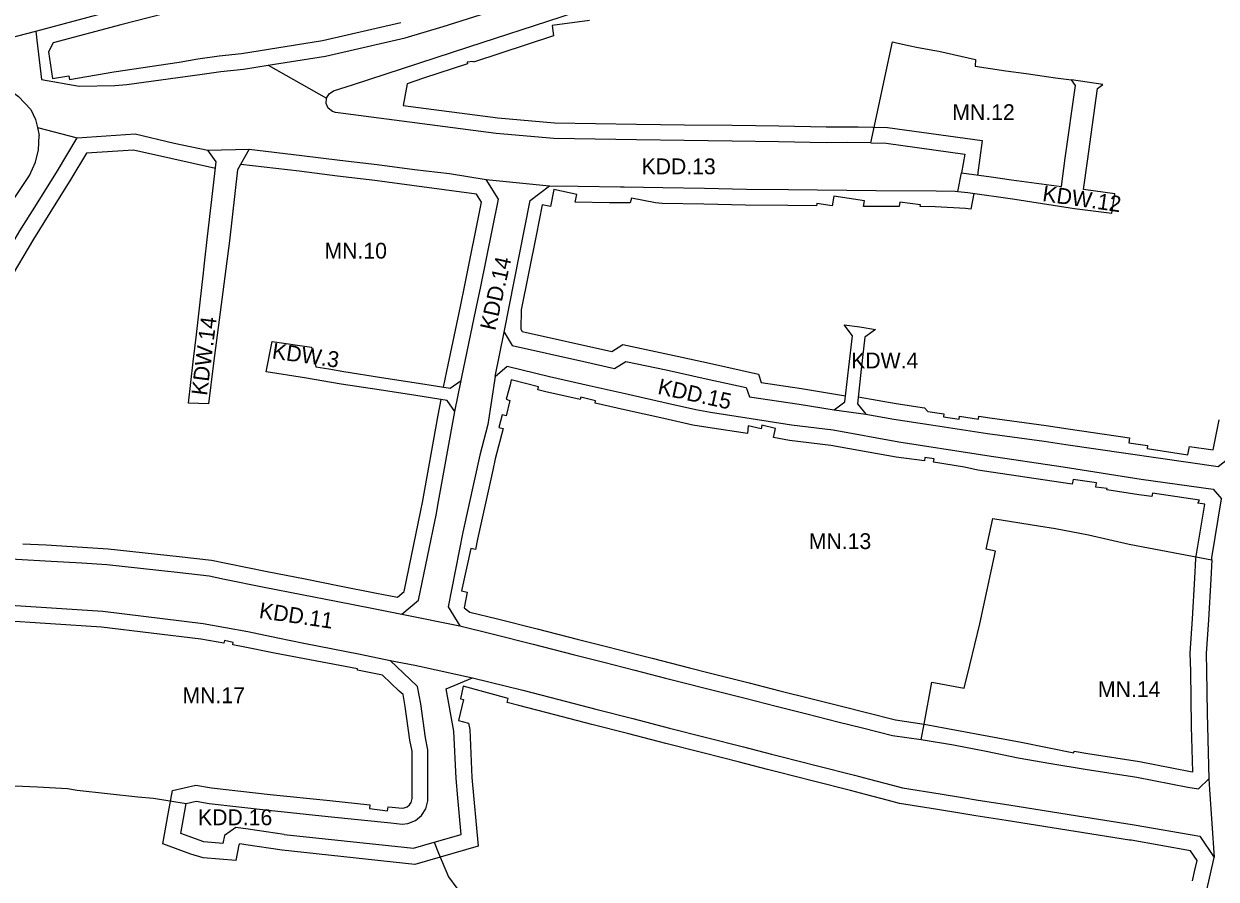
# Model space of a CAD drawing. Extents: x 7414808 to 7417449, y 5544732 to 5546764.
# Drawn here: x 7415519.6 to 7415895.6, y 5545621.3 to 5545891.1 of the extents above; entities that cross this region are included whole.
import ezdxf

# ---------------------------------------------------------------- set-up
doc = ezdxf.new("R2010")
doc.units = 0
for name, color, linetype in [('LIN_Linie Rozgraniczajace', 7, 'Continuous'), ('LIN_nieprzekraczale linie zabudowy', 7, 'Continuous'), ('TXT_Oznaczenia Przeznaczenia', 7, 'Continuous')]:
    doc.layers.add(name, color=color, linetype=linetype)

msp = doc.modelspace()

# ---------------------------------------------------------------- linework, layer by layer
at = {"layer": 'LIN_Linie Rozgraniczajace'}
for p, q in [((7415596.59, 5545878.03), (7415614.98, 5545867.62)), ((7415523.85, 5545858.38), (7415536.38, 5545855.13)), ((7415577.65, 5545851.21), (7415590.67, 5545851.56)), ((7415814.2, 5545838.2), (7415815.27, 5545844.11))]:
    msp.add_line(p, q, dxfattribs=at)
for points in [[(7415523.4, 5545888.77), (7415548.92, 5545895.57), (7415571.98, 5545901.49), (7415578.52, 5545903.17), (7415594.12, 5545907.16), (7415632.68, 5545916.73), (7415649.68, 5545921.35), (7415662.13, 5545924.72), (7415674.21, 5545927.99), (7415712.72, 5545938), (7415729.3, 5545942.15), (7415745.31, 5545946.18), (7415747.25, 5545946.68), (7415766.4, 5545951.66), (7415766.99, 5545951.81), (7415774, 5545953.91), (7415784.27, 5545956.51), (7415802.62, 5545961.02)], [(7415614.98, 5545867.62), (7415615.82, 5545869.06), (7415617.23, 5545869.94), (7415617.57, 5545870.05), (7415623.24, 5545871.85), (7415644.1, 5545878.69), (7415659.92, 5545883.83), (7415689.07, 5545893.3), (7415697.47, 5545896.12), (7415715.84, 5545901.77), (7415777.73, 5545917.93), (7415789.12, 5545920.23), (7415796.38, 5545921.71), (7415807.79, 5545922.67), (7415823.09, 5545924.04), (7415837.24, 5545927.04), (7415849.99, 5545929.82), (7415855.28, 5545930.97), (7415862.77, 5545932.27), (7415883.2, 5545935.59), (7415887.87, 5545936.49), (7415911.39, 5545942.72)], [(7415596.59, 5545878.03), (7415614.73, 5545880.93), (7415639.79, 5545886.66), (7415651.81, 5545890.22), (7415669.44, 5545895.85), (7415670.41, 5545896.15), (7415681.78, 5545899.54), (7415718.18, 5545910.49), (7415731.5, 5545914.06), (7415750.14, 5545919.17), (7415770.99, 5545924.57), (7415776.17, 5545925.79), (7415779.64, 5545926.58), (7415788.05, 5545928.54), (7415788.96, 5545929.82), (7415809.43, 5545932.85)], [(7415477.36, 5545876.7), (7415488.81, 5545879.82), (7415523.4, 5545888.77)], [(7415523.4, 5545888.77), (7415523.72, 5545885.89), (7415525.14, 5545873.58), (7415537, 5545871.48), (7415548.29, 5545871.62), (7415552.1, 5545871.93), (7415568.11, 5545874.17), (7415575.12, 5545875.15), (7415581.75, 5545876.08), (7415588.81, 5545876.78), (7415596.59, 5545878.03)], [(7415786.7, 5545853.51), (7415793.56, 5545885.38), (7415794.39, 5545885.2), (7415798.64, 5545884.25), (7415801.68, 5545883.66), (7415806.89, 5545882.66), (7415808.15, 5545882.42), (7415819.75, 5545879.88), (7415819.61, 5545877.69), (7415829.33, 5545876.31), (7415835.7, 5545875.41), (7415842.1, 5545874.49), (7415844.94, 5545874.09), (7415849.96, 5545873.38)], [(7415477.36, 5545876.7), (7415482.86, 5545875.66), (7415499.48, 5545872.28), (7415512.05, 5545871.46), (7415515.09, 5545870.26), (7415517.91, 5545868.19), (7415521.74, 5545864.02), (7415523.26, 5545860.87), (7415523.85, 5545858.38), (7415524.45, 5545855.9)], [(7415814.2, 5545838.2), (7415817.26, 5545837.87), (7415832.14, 5545835.74), (7415849.62, 5545833.02), (7415850.91, 5545832.82), (7415862.77, 5545831.38), (7415863.63, 5545837.43), (7415853.78, 5545838.79), (7415855, 5545847.8), (7415858.16, 5545870.7), (7415859.85, 5545871.98), (7415849.96, 5545873.38)], [(7415815.27, 5545844.11), (7415824.66, 5545842.81), (7415831.1, 5545841.92), (7415837.42, 5545841.05), (7415846.82, 5545839.75), (7415848.04, 5545848.74), (7415851.23, 5545871.69), (7415849.96, 5545873.38)], [(7415786.7, 5545853.51), (7415779.22, 5545853.62), (7415772.59, 5545853.56), (7415757.6, 5545853.87), (7415742.94, 5545854.08), (7415727.84, 5545854.28), (7415712.76, 5545854.49), (7415686.68, 5545854.9), (7415668.52, 5545856.47), (7415617.87, 5545863.14), (7415616.88, 5545863.43), (7415615.58, 5545864.45), (7415614.89, 5545865.97), (7415614.98, 5545867.62)], [(7415480.78, 5545727.12), (7415483.24, 5545729.05), (7415482.96, 5545743.71), (7415483.01, 5545750.02), (7415483.36, 5545755.98), (7415483.69, 5545759.38), (7415484.11, 5545762.65), (7415484.85, 5545767.3), (7415485.36, 5545769.95), (7415486, 5545772.89), (7415486.78, 5545776.08), (7415487.58, 5545779), (7415488.59, 5545782.35), (7415489.61, 5545785.4), (7415494.82, 5545800.38), (7415495.83, 5545803.08), (7415496.97, 5545805.76), (7415498.25, 5545808.39), (7415499.87, 5545811.19), (7415501.45, 5545813.54), (7415521.39, 5545843.2), (7415523.29, 5545847.45), (7415524.15, 5545851.33), (7415524.45, 5545855.9)], [(7415493.88, 5545723.56), (7415491.6, 5545726.46), (7415491.04, 5545743.03), (7415491.05, 5545746.02), (7415491.44, 5545755.02), (7415491.83, 5545759.76), (7415492.93, 5545767.37), (7415493.22, 5545768.86), (7415494.06, 5545772.67), (7415495.16, 5545776.83), (7415496.15, 5545780.07), (7415496.98, 5545782.52), (7415497.64, 5545784.32), (7415500.03, 5545790.71), (7415501.74, 5545794.67), (7415503.69, 5545798.77), (7415510.12, 5545811.91), (7415518.31, 5545825.81), (7415523.57, 5545834.09), (7415530.15, 5545844.72), (7415536.38, 5545855.13)], [(7415536.38, 5545855.13), (7415554.72, 5545856.36), (7415566.99, 5545853.46), (7415577.65, 5545851.21)], [(7415590.67, 5545851.56), (7415586.99, 5545845.02), (7415584.47, 5545822.61), (7415579.37, 5545784.03), (7415577.86, 5545771.26), (7415571.53, 5545771.44), (7415573, 5545784.48), (7415573.98, 5545793.13), (7415576.22, 5545812.5), (7415576.58, 5545815.58), (7415577.55, 5545824.03), (7415578.89, 5545835.66), (7415580.26, 5545847.57), (7415577.65, 5545851.21)], [(7415590.67, 5545851.56), (7415607.22, 5545849.6), (7415619.27, 5545848.06), (7415631.06, 5545846.69), (7415642.77, 5545845.11), (7415653.86, 5545843.84), (7415665.34, 5545842.04)], [(7415786.7, 5545853.51), (7415791.53, 5545853.45), (7415816.35, 5545850.02), (7415815.27, 5545844.11)], [(7415657.47, 5545778.62), (7415657.67, 5545779.6), (7415662.15, 5545800.85), (7415663.59, 5545807.7), (7415669.24, 5545835.78), (7415665.34, 5545842.04)], [(7415665.34, 5545842.04), (7415685.32, 5545839.97)], [(7415671.03, 5545793.81), (7415675.95, 5545818.35), (7415679.27, 5545835.4), (7415685.32, 5545839.97)], [(7415685.32, 5545839.97), (7415694.45, 5545839.86), (7415707.74, 5545839.69), (7415708.86, 5545839.67), (7415721.14, 5545839.49), (7415734.27, 5545839.24), (7415747.45, 5545838.95), (7415760.71, 5545838.82), (7415788.27, 5545838.53), (7415807.34, 5545838.46), (7415813.32, 5545838.3), (7415814.2, 5545838.2)], [(7415775.16, 5545769.3), (7415778.55, 5545771.84), (7415779.78, 5545782.81), (7415780.89, 5545792.71), (7415778.29, 5545796.16), (7415783.24, 5545795.47), (7415788.18, 5545794.67), (7415784.82, 5545792.27), (7415783.69, 5545782.21), (7415782.46, 5545771.23), (7415785.08, 5545767.93)], [(7415655.49, 5545768.8), (7415653.13, 5545772.26), (7415643.24, 5545773.82), (7415631.6, 5545775.61), (7415619.69, 5545777.46), (7415608.05, 5545779.42), (7415595.99, 5545781.37), (7415597.91, 5545790.89), (7415610.25, 5545789.14), (7415611.65, 5545782.93), (7415615.73, 5545782.22), (7415620.48, 5545781.39), (7415632.36, 5545779.56), (7415644.08, 5545777.75), (7415653.99, 5545776.16), (7415657.47, 5545778.62)], [(7415668.24, 5545779.8), (7415671.03, 5545793.81)], [(7415671.03, 5545793.81), (7415673.64, 5545789.58), (7415696.16, 5545784.56), (7415705.9, 5545782.39), (7415709.42, 5545784.59), (7415722.18, 5545781.91), (7415734.77, 5545779.16), (7415747.43, 5545776.33), (7415748.41, 5545773.42), (7415764.07, 5545771.09), (7415775.16, 5545769.3)], [(7415668.24, 5545779.8), (7415672.05, 5545783.11), (7415685.34, 5545779.85), (7415697.83, 5545777.04), (7415710.13, 5545774.26), (7415722.57, 5545771.47), (7415731.5, 5545769.45), (7415736.13, 5545768.65), (7415748.95, 5545766.65), (7415761.72, 5545764.58), (7415774.82, 5545763.02), (7415795.49, 5545759.28), (7415821.27, 5545755.23), (7415823.26, 5545754.92), (7415847.35, 5545751.4), (7415871.95, 5545747.49), (7415894.72, 5545744.26), (7415897.34, 5545741.25)], [(7415668.24, 5545779.8), (7415665.93, 5545764.68), (7415663.4, 5545755.01), (7415658.01, 5545730.74), (7415653.38, 5545707.15), (7415657.04, 5545701.19)], [(7415655.49, 5545768.8), (7415657.47, 5545778.62)], [(7415638.79, 5545704.93), (7415644.02, 5545709.25), (7415649.74, 5545736.68), (7415650.19, 5545739.24), (7415655.49, 5545768.8)], [(7415775.16, 5545769.3), (7415785.08, 5545767.93)], [(7415785.08, 5545767.93), (7415793.95, 5545766.44), (7415805.7, 5545764.63), (7415823.54, 5545761.88), (7415841.33, 5545759.46), (7415848.19, 5545758.4), (7415896.23, 5545751.46), (7415899.18, 5545753.76)], [(7415894.25, 5545722.05), (7415894.28, 5545722.62), (7415897.34, 5545741.25)], [(7415802.59, 5545665.35), (7415803.51, 5545670.22), (7415805.94, 5545683.39), (7415816.14, 5545681.53), (7415817.93, 5545688.84), (7415821.11, 5545701.86), (7415826.05, 5545724.77), (7415823.13, 5545725.4), (7415825.22, 5545735.1), (7415839.64, 5545732.77), (7415844.92, 5545731.92), (7415855.39, 5545729.92), (7415868.14, 5545726.99), (7415894.25, 5545722.05)], [(7415493.88, 5545723.56), (7415519.01, 5545722.12), (7415526.34, 5545721.71), (7415537.82, 5545721.02), (7415545.75, 5545720.55), (7415567.96, 5545718.09), (7415577.98, 5545716.99), (7415582.85, 5545715.92), (7415595.35, 5545713.4), (7415607.29, 5545711.07), (7415618.11, 5545708.93), (7415629.85, 5545706.62), (7415638.79, 5545704.93)], [(7415894.25, 5545722.05), (7415893.91, 5545715.94), (7415893.19, 5545703.07), (7415892.45, 5545692.5), (7415892.62, 5545686.97), (7415892.8, 5545673.63), (7415892.88, 5545669.58), (7415893.33, 5545652.97)], [(7415495.61, 5545708.97), (7415512.11, 5545707.9), (7415544.5, 5545705.8), (7415576.18, 5545701.95), (7415590.24, 5545699.42), (7415599.66, 5545697.46), (7415607.83, 5545695.76), (7415625.63, 5545692.21), (7415635.08, 5545690.22)], [(7415638.79, 5545704.93), (7415657.04, 5545701.19)], [(7415657.04, 5545701.19), (7415667.69, 5545698.52), (7415680.26, 5545695.37), (7415692.83, 5545692.12), (7415702.55, 5545689.77), (7415712.24, 5545687.24), (7415721.91, 5545684.73), (7415728.24, 5545683.13), (7415734.46, 5545681.55), (7415747.09, 5545678.36), (7415756.8, 5545675.85), (7415766.53, 5545673.39), (7415776.27, 5545670.96), (7415784.11, 5545669), (7415793.51, 5545666.63), (7415802.59, 5545665.35)], [(7415570.82, 5545645.14), (7415573.92, 5545645.86), (7415578.02, 5545645.11), (7415596.69, 5545643.05), (7415615.53, 5545641.08), (7415635.27, 5545639.01), (7415638.94, 5545638.64), (7415640.73, 5545638.86), (7415643.07, 5545639.78), (7415645.02, 5545641.39), (7415646.36, 5545643.52), (7415646.98, 5545645.97), (7415647.01, 5545646.67), (7415647.01, 5545653.46), (7415647, 5545656.56), (7415647, 5545659.16), (7415647, 5545662.07), (7415646.3, 5545665.9), (7415644.8, 5545676.55), (7415643.77, 5545682.06), (7415641.42, 5545684.25), (7415635.08, 5545690.22)], [(7415635.08, 5545690.22), (7415642.92, 5545688.78), (7415644.32, 5545688.48), (7415661.05, 5545684.82)], [(7415648.98, 5545632.92), (7415657.48, 5545635.39), (7415656.44, 5545646.99), (7415655.9, 5545652.99), (7415655.23, 5545667.92), (7415652.73, 5545681.37), (7415661.05, 5545684.82)], [(7415661.05, 5545684.82), (7415676.93, 5545680.92), (7415688.35, 5545677.97), (7415699.97, 5545674.87), (7415711.6, 5545671.92), (7415723.25, 5545668.92), (7415734.93, 5545665.97), (7415746.53, 5545663.01), (7415755.42, 5545660.72), (7415758.33, 5545659.97), (7415769.89, 5545657.07), (7415781.57, 5545654.1), (7415786.31, 5545652.8), (7415793.16, 5545651.01), (7415796.73, 5545650.09), (7415808.55, 5545648.18), (7415815.62, 5545647.04), (7415820.59, 5545646.25), (7415830.2, 5545644.71), (7415851.89, 5545641.29), (7415869.18, 5545638.57), (7415869.76, 5545638.46), (7415890.46, 5545634.8), (7415894.95, 5545628.13)], [(7415802.59, 5545665.35), (7415812.74, 5545663.63), (7415823.1, 5545661.63), (7415833.22, 5545659.59), (7415843.5, 5545657.79), (7415854.35, 5545656.01), (7415870.6, 5545653.48), (7415886.65, 5545650.33), (7415890.01, 5545649.73), (7415893.33, 5545652.97)], [(7415893.33, 5545652.97), (7415893.55, 5545649.56), (7415894.95, 5545628.13)], [(7415491.71, 5545650.6), (7415509.49, 5545651.06), (7415523.88, 5545650.45), (7415533.32, 5545649.87), (7415536.34, 5545649.36), (7415555.51, 5545647.21), (7415560.5, 5545646.8), (7415570.82, 5545645.14)], [(7415601.67, 5545635.42), (7415590.32, 5545637.1), (7415586.43, 5545637.61), (7415582.87, 5545635.06), (7415582.38, 5545632.56), (7415576.38, 5545633.08), (7415569.07, 5545635.73), (7415570.82, 5545645.14)], [(7415601.67, 5545635.42), (7415639.48, 5545631.35), (7415642.46, 5545631.03), (7415648.98, 5545632.92)], [(7415648.98, 5545632.92), (7415650.4, 5545629.46), (7415653.49, 5545621.97), (7415658.73, 5545614.91), (7415666.77, 5545610.81), (7415668.49, 5545609.94)], [(7415870.59, 5545572.43), (7415878.77, 5545578.95), (7415882.02, 5545583.17), (7415885.02, 5545587.08), (7415887.46, 5545593.96), (7415888.71, 5545597.14), (7415890.86, 5545610.04), (7415893.79, 5545623.01), (7415894.95, 5545628.13)]]:
    msp.add_lwpolyline(points, dxfattribs=at)
at = {"layer": 'LIN_nieprzekraczale linie zabudowy'}
for points in [[(7415573.22, 5545896.65), (7415550.19, 5545890.73), (7415528.86, 5545885.05), (7415527.3, 5545882.31), (7415528.61, 5545873.81), (7415533.78, 5545874.64), (7415533.96, 5545873.58), (7415547.99, 5545875.94), (7415568.55, 5545879.04), (7415574.43, 5545880.1), (7415581.16, 5545881.05), (7415588.17, 5545881.74), (7415613.78, 5545885.84), (7415638.52, 5545891.5)], [(7415697.96, 5545892.11), (7415686.2, 5545890.6), (7415686.67, 5545887.27), (7415661.34, 5545879.03), (7415661.31, 5545879.25), (7415659.42, 5545878.95), (7415659.48, 5545878.43), (7415645.65, 5545873.93), (7415640.42, 5545872.22), (7415639.23, 5545865.37), (7415669.06, 5545861.44), (7415686.93, 5545859.9), (7415712.83, 5545859.49), (7415727.91, 5545859.28), (7415743.01, 5545859.08), (7415757.69, 5545858.87), (7415772.62, 5545858.56), (7415779.23, 5545858.62), (7415782.67, 5545858.57), (7415791.97, 5545858.43)], [(7415791.97, 5545858.43), (7415821.82, 5545854.31), (7415820.37, 5545843.4)], [(7415580.02, 5545845.48), (7415565.89, 5545848.58), (7415554.15, 5545851.27), (7415539.3, 5545850.27)], [(7415539.3, 5545850.27), (7415534.42, 5545842.12), (7415527.81, 5545831.43), (7415522.58, 5545823.2), (7415514.53, 5545809.54)], [(7415651.94, 5545776.49), (7415652.97, 5545781.57), (7415657.26, 5545801.88), (7415658.69, 5545808.71), (7415663.95, 5545834.82), (7415662.39, 5545837.32), (7415641.93, 5545840.1), (7415630.26, 5545841.68), (7415618.49, 5545843.06), (7415606.44, 5545844.58), (7415587.98, 5545846.77)], [(7415704.26, 5545834.68), (7415693.44, 5545834.81), (7415693.94, 5545837.24), (7415686.78, 5545838.83), (7415685.66, 5545833.43), (7415683.07, 5545834), (7415681.2, 5545824.31), (7415676.39, 5545800.92), (7415676.32, 5545794.76), (7415676.79, 5545794), (7415704.99, 5545787.72), (7415708.48, 5545789.9), (7415723.23, 5545786.8), (7415735.85, 5545784.04), (7415751.27, 5545780.6), (7415752.17, 5545777.92), (7415764.84, 5545776.03), (7415778.77, 5545773.78)], [(7415819.17, 5545837.6), (7415818.26, 5545832.6), (7415816.58, 5545832.84), (7415807.01, 5545833.41), (7415802.31, 5545833.43), (7415802.36, 5545833.95), (7415795.86, 5545834.79), (7415795.68, 5545833.45), (7415788.06, 5545833.48), (7415784.44, 5545833.52), (7415784.73, 5545835.3), (7415775.06, 5545836.77), (7415774.56, 5545833.69), (7415769.68, 5545834.44), (7415769.57, 5545833.67), (7415760.49, 5545833.77), (7415747.2, 5545833.9), (7415734, 5545834.19), (7415720.88, 5545834.44), (7415718.77, 5545834.63), (7415711.19, 5545836.14), (7415710.85, 5545834.59), (7415708.61, 5545834.62), (7415707.49, 5545834.64), (7415704.26, 5545834.68)], [(7415892, 5545739.6), (7415889.88, 5545739.9), (7415890.33, 5545740.88), (7415875.51, 5545743.03), (7415875.35, 5545741.96), (7415871.21, 5545742.55), (7415861.15, 5545744.14), (7415861.21, 5545744.56), (7415857.69, 5545744.98), (7415857.92, 5545746.3), (7415850.49, 5545747.4), (7415850.25, 5545745.88), (7415846.6, 5545746.46), (7415822.51, 5545749.98), (7415820.5, 5545750.29), (7415816.26, 5545751.24), (7415806.52, 5545752.82), (7415806.68, 5545753.9), (7415803.76, 5545754.3), (7415803.59, 5545753.2), (7415794.66, 5545754.35), (7415774.08, 5545758.07), (7415761.02, 5545759.63), (7415755.98, 5545760.62), (7415756.6, 5545763.49), (7415752.33, 5545764.45), (7415752.08, 5545763.37), (7415747.97, 5545764.32), (7415747.77, 5545761.83), (7415735.32, 5545763.72), (7415730.52, 5545764.54), (7415721.47, 5545766.59), (7415709.03, 5545769.38), (7415699.76, 5545771.48), (7415699.92, 5545772.21), (7415695.2, 5545773.33), (7415695, 5545772.55), (7415684.2, 5545774.98), (7415681.68, 5545775.6), (7415681.9, 5545776.57), (7415673.22, 5545778.76), (7415672.91, 5545777.23), (7415671.67, 5545772.7), (7415672.84, 5545772.33), (7415671.71, 5545767.45), (7415670.42, 5545767.71), (7415669.42, 5545763.75), (7415670.77, 5545763.41), (7415668.26, 5545753.84), (7415667.47, 5545750.28), (7415662.67, 5545728.53), (7415662.03, 5545725.27), (7415660.5, 5545725.56), (7415657.61, 5545712.24), (7415659.4, 5545711.87), (7415658.43, 5545706.91), (7415660.23, 5545705.54), (7415668.91, 5545703.37), (7415681.49, 5545700.22), (7415694.04, 5545696.97), (7415703.77, 5545694.62), (7415713.52, 5545692.07), (7415717.71, 5545690.95), (7415729.47, 5545687.98), (7415735.69, 5545686.4), (7415748.33, 5545683.2), (7415758.04, 5545680.69), (7415767.75, 5545678.24), (7415777.48, 5545675.81), (7415785.33, 5545673.85), (7415794.47, 5545671.54), (7415803.51, 5545670.22), (7415834.15, 5545664.5), (7415850.69, 5545661.15), (7415850.79, 5545661.66), (7415855.14, 5545660.95), (7415871.47, 5545658.41), (7415887.57, 5545655.24), (7415888.27, 5545655.12), (7415887.88, 5545669.44), (7415887.88, 5545669.51), (7415887.62, 5545686.86), (7415887.44, 5545692.6), (7415888.2, 5545703.38), (7415888.92, 5545716.22), (7415889.26, 5545722.33), (7415889.26, 5545722.31), (7415889.3, 5545723.16), (7415892, 5545739.6)], [(7415519.29, 5545727.11), (7415526.63, 5545726.7), (7415538.12, 5545726.01), (7415546.17, 5545725.53), (7415568.51, 5545723.06), (7415578.79, 5545721.93), (7415583.88, 5545720.81), (7415596.32, 5545718.3), (7415608.25, 5545715.98), (7415619.08, 5545713.84), (7415630.8, 5545711.53), (7415637.41, 5545710.28), (7415639.48, 5545711.99), (7415644.83, 5545737.62), (7415645.27, 5545740.11), (7415650.21, 5545767.66), (7415651.15, 5545772.57)], [(7415782.7, 5545773.4), (7415794.74, 5545771.38), (7415803.61, 5545770.01), (7415804.66, 5545768.83), (7415809.78, 5545768.05), (7415809.64, 5545767.12), (7415814.6, 5545766.35), (7415814.72, 5545767.29), (7415820.66, 5545766.38), (7415820.81, 5545767.36), (7415824.26, 5545766.83), (7415842.05, 5545764.41), (7415848.93, 5545763.35), (7415868.32, 5545760.54), (7415868.06, 5545758.93), (7415873.98, 5545758.1), (7415873.83, 5545757.11), (7415886.7, 5545755.18), (7415887.22, 5545757.81), (7415894.67, 5545756.74), (7415896.53, 5545766.18)], [(7415888.17, 5545620.81), (7415888.91, 5545624.11), (7415889.6, 5545627.13), (7415887.5, 5545630.25), (7415868.86, 5545633.54), (7415868.33, 5545633.64), (7415851.11, 5545636.35), (7415829.42, 5545639.77), (7415819.8, 5545641.31), (7415814.83, 5545642.1), (7415807.75, 5545643.24), (7415795.71, 5545645.19), (7415791.9, 5545646.17), (7415785.02, 5545647.97), (7415780.29, 5545649.27), (7415768.67, 5545652.22), (7415757.1, 5545655.12), (7415754.17, 5545655.88), (7415745.29, 5545658.17), (7415733.7, 5545661.12), (7415722.01, 5545664.08), (7415710.36, 5545667.08), (7415698.71, 5545670.03), (7415687.08, 5545673.13), (7415675.71, 5545676.07), (7415671.97, 5545676.99), (7415672.31, 5545678.29), (7415658.18, 5545682.12), (7415657.26, 5545678.21), (7415658.27, 5545677.97), (7415656.65, 5545671.32), (7415659.84, 5545670.5), (7415659.84, 5545670.5), (7415660.21, 5545668.49), (7415660.89, 5545653.33), (7415662.83, 5545631.74), (7415642.91, 5545625.95), (7415601.04, 5545630.46), (7415589.63, 5545632.15), (7415587.74, 5545632.4), (7415587.39, 5545632.15), (7415586.41, 5545627.19), (7415576.16, 5545628.02), (7415572.23, 5545629.14), (7415563.38, 5545632.47), (7415565.22, 5545642.38), (7415566.5, 5545649.27), (7415573.8, 5545650.97), (7415578.74, 5545650.06), (7415597.22, 5545648.02), (7415616.05, 5545646.05), (7415628.74, 5545644.72), (7415628.59, 5545643.62), (7415634.27, 5545642.86), (7415634.47, 5545644.12), (7415635.78, 5545643.98), (7415638.88, 5545643.67), (7415639.49, 5545643.74), (7415640.5, 5545644.14), (7415641.21, 5545644.73), (7415641.71, 5545645.52), (7415642.01, 5545646.71), (7415642.01, 5545646.71), (7415642.01, 5545653.45), (7415642, 5545656.55), (7415642, 5545659.16), (7415642, 5545661.62), (7415641.36, 5545665.1), (7415639.86, 5545675.74), (7415639.16, 5545679.52), (7415638, 5545680.6), (7415632.68, 5545685.62), (7415624.76, 5545687.23), (7415624.79, 5545687.68), (7415598.64, 5545692.56), (7415589.29, 5545694.51), (7415585.5, 5545695.19), (7415585.5, 5545695.19), (7415585.63, 5545695.93), (7415582.88, 5545696.53), (7415582.69, 5545695.7), (7415582.69, 5545695.7), (7415575.44, 5545697), (7415544.04, 5545700.82), (7415511.79, 5545702.91)]]:
    msp.add_lwpolyline(points, dxfattribs=at)

# ---------------------------------------------------------------- texts
at = {"layer": 'TXT_Oznaczenia Przeznaczenia'}
for s, p in [('MN.12', (7415812.41, 5545860.72)), ('KDD.13', (7415714.38, 5545843.64)), ('MN.10', (7415614.4, 5545817.03)), ('KDW.4', (7415780.5, 5545782.41)), ('MN.13', (7415767.14, 5545725.41)), ('MN.17', (7415569.62, 5545676.8)), ('MN.14', (7415858.35, 5545678.71)), ('KDD.16', (7415574.51, 5545638.3))]:
    msp.add_text(s, height=5, dxfattribs=at).set_placement(p)
for s, rotation, p in [('KDW.12', 351.8055, (7415840.61, 5545835.21)), ('KDD.14', 77.4025, (7415668.26, 5545794.11)), ('KDW.14', 82.8831, (7415577.33, 5545773.66)), ('KDW.3', 352, (7415597.66, 5545785.55)), ('KDD.15', 347.7267, (7415719.22, 5545774.4)), ('KDD.11', 351.5528, (7415593.55, 5545703.71))]:
    msp.add_text(s, height=5, rotation=rotation, dxfattribs=at).set_placement(p)

doc.saveas('drawing.dxf')
